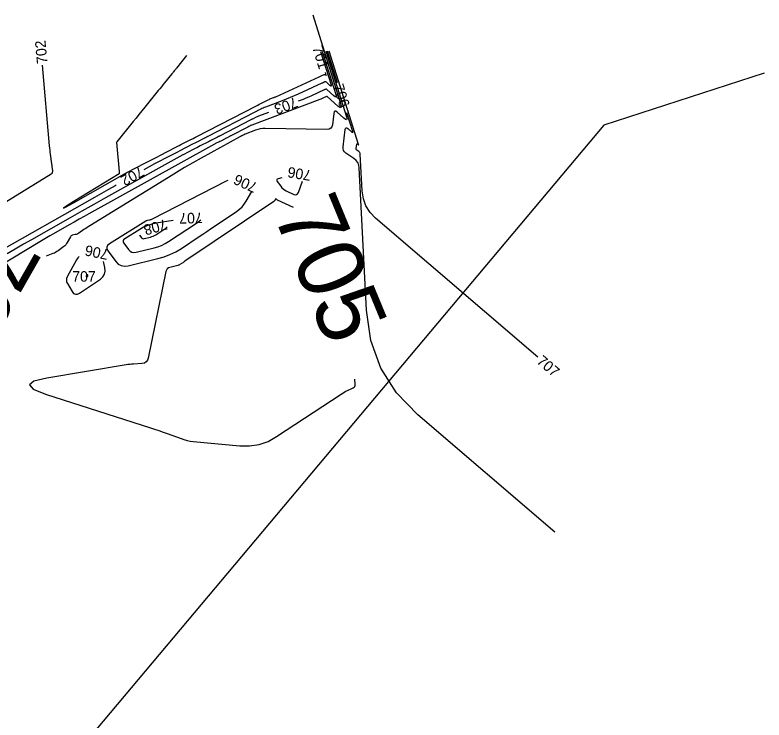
# Model space of a CAD drawing. Extents: x -468541894 to 3393103, y -306086142 to 1227927.
# Drawn here: x 1843241.8 to 1843525.9, y 539482.8 to 539750.1 of the extents above; entities that cross this region are included whole.
import ezdxf

# ---------------------------------------------------------------- set-up
doc = ezdxf.new("R2010")
doc.units = 0
for name, color, linetype in [('DT_X_Contour_Minor', 7, 'Continuous'), ('Level 19', 7, 'Continuous'), ('Level 40', 7, 'Continuous')]:
    doc.layers.add(name, color=color, linetype=linetype)

msp = doc.modelspace()

# ---------------------------------------------------------------- linework, layer by layer
at = {"layer": 'DT_X_Contour_Minor'}
for points in [[(1843354.69, 539750.11), (1843365.34, 539716.2), (1843365.54, 539715.31), (1843365.43, 539714.9), (1843365.01, 539714.97), (1843364.29, 539715.53), (1843360.23, 539719.22), (1843360.2, 539719.24), (1843360.18, 539719.25), (1843360.15, 539719.25), (1843360.12, 539719.24), (1843360.03, 539719.2), (1843360.01, 539719.19), (1843359.99, 539719.18), (1843359.97, 539719.17), (1843359.95, 539719.16), (1843358.6, 539718.54), (1843358.31, 539718.42), (1843358.02, 539718.29), (1843357.73, 539718.17), (1843357.43, 539718.06), (1843331.61, 539708.35), (1843331.45, 539708.29), (1843331.3, 539708.22), (1843331.14, 539708.15), (1843330.99, 539708.08), (1843330.49, 539707.82), (1843330.38, 539707.76), (1843330.27, 539707.71), (1843330.16, 539707.65), (1843330.06, 539707.6), (1843323.67, 539704.31), (1843323.62, 539704.28), (1843323.56, 539704.25), (1843323.51, 539704.22), (1843323.45, 539704.2), (1843323.28, 539704.1), (1843323.24, 539704.08), (1843323.2, 539704.07), (1843323.16, 539704.05), (1843323.12, 539704.03), (1843322.23, 539703.56), (1843322.03, 539703.46), (1843321.84, 539703.37), (1843321.65, 539703.27), (1843321.46, 539703.17), (1843319.8, 539702.31), (1843319.44, 539702.13), (1843319.08, 539701.94), (1843318.73, 539701.76), (1843318.37, 539701.58), (1843316.35, 539700.54), (1843316.34, 539700.53), (1843316.33, 539700.53), (1843316.33, 539700.52), (1843316.32, 539700.52), (1843316.29, 539700.51), (1843316.29, 539700.5), (1843316.28, 539700.5), (1843316.28, 539700.5), (1843316.27, 539700.49), (1843269.84, 539674.71), (1843267.97, 539673.67), (1843266.11, 539672.63), (1843264.25, 539671.59), (1843262.4, 539670.54), (1843256.34, 539667.1), (1843255.05, 539666.36), (1843253.76, 539665.61), (1843252.47, 539664.86), (1843251.19, 539664.09), (1843225.15, 539648.36)], [(1843359.68, 539736.36), (1843367.47, 539711.54), (1843367.65, 539710.75), (1843367.55, 539710.39), (1843367.18, 539710.45), (1843366.54, 539710.95), (1843364.01, 539713.25), (1843363.52, 539713.6), (1843363.14, 539713.63), (1843362.88, 539713.36), (1843362.73, 539712.78), (1843362.19, 539708.5), (1843361.97, 539707.7), (1843361.55, 539707.13), (1843360.93, 539706.8), (1843360.11, 539706.7), (1843336.66, 539707.08), (1843335.74, 539707.05), (1843334.83, 539706.94), (1843333.94, 539706.74), (1843333.07, 539706.46), (1843329.05, 539704.95), (1843329.03, 539704.94), (1843329.01, 539704.93), (1843328.99, 539704.92), (1843328.97, 539704.91), (1843328.9, 539704.88), (1843328.89, 539704.87), (1843328.88, 539704.86), (1843328.86, 539704.86), (1843328.85, 539704.85), (1843328.02, 539704.42), (1843328.01, 539704.42), (1843328.01, 539704.42), (1843328, 539704.41), (1843327.99, 539704.41), (1843327.97, 539704.4), (1843327.97, 539704.39), (1843327.96, 539704.39), (1843327.96, 539704.39), (1843327.95, 539704.39), (1843327.83, 539704.33), (1843327.81, 539704.31), (1843327.78, 539704.3), (1843327.76, 539704.29), (1843327.73, 539704.28), (1843327.52, 539704.17), (1843327.47, 539704.14), (1843327.43, 539704.12), (1843327.38, 539704.09), (1843327.34, 539704.07), (1843327.07, 539703.94), (1843327.07, 539703.93), (1843327.07, 539703.93), (1843327.07, 539703.93), (1843327.07, 539703.93), (1843327.07, 539703.93), (1843327.07, 539703.93), (1843327.06, 539703.93), (1843327.06, 539703.93), (1843327.06, 539703.93), (1843312.39, 539695.78), (1843309.26, 539694.02), (1843306.14, 539692.22), (1843303.05, 539690.39), (1843299.98, 539688.52), (1843270.14, 539670.15), (1843269.58, 539669.8), (1843269.02, 539669.45), (1843268.47, 539669.08), (1843267.92, 539668.71), (1843265.96, 539667.37), (1843265.66, 539667.18), (1843265.34, 539667.03), (1843265.01, 539666.9), (1843264.67, 539666.81), (1843263.52, 539666.57), (1843263.29, 539666.5), (1843263.09, 539666.38), (1843262.93, 539666.22), (1843262.79, 539666.02), (1843261.63, 539663.86), (1843261.36, 539663.41), (1843261.05, 539663), (1843260.69, 539662.63), (1843260.29, 539662.3), (1843258.17, 539660.7), (1843257.71, 539660.38), (1843257.22, 539660.09), (1843256.72, 539659.84), (1843256.2, 539659.63), (1843253.64, 539658.68)], [(1843357.69, 539736.29), (1843361.66, 539723.63), (1843361.74, 539723.28), (1843361.7, 539723.11), (1843361.53, 539723.14), (1843361.24, 539723.37), (1843359.89, 539724.6), (1843359.74, 539724.7), (1843359.58, 539724.75), (1843359.42, 539724.75), (1843359.24, 539724.7), (1843358.66, 539724.43), (1843358.53, 539724.37), (1843358.41, 539724.31), (1843358.28, 539724.26), (1843358.15, 539724.2), (1843349.19, 539720.09), (1843347.68, 539719.42), (1843346.16, 539718.77), (1843344.63, 539718.15), (1843343.09, 539717.55), (1843336.74, 539715.17), (1843336.3, 539715), (1843335.87, 539714.81), (1843335.44, 539714.61), (1843335.02, 539714.4), (1843333.65, 539713.7), (1843333.36, 539713.55), (1843333.06, 539713.4), (1843332.77, 539713.24), (1843332.47, 539713.09), (1843314.98, 539704.08), (1843314.83, 539704), (1843314.68, 539703.92), (1843314.53, 539703.85), (1843314.38, 539703.77), (1843313.89, 539703.52), (1843313.78, 539703.46), (1843313.68, 539703.41), (1843313.57, 539703.36), (1843313.47, 539703.3), (1843311.01, 539702.04), (1843310.49, 539701.77), (1843309.96, 539701.49), (1843309.43, 539701.22), (1843308.91, 539700.95), (1843304.35, 539698.6), (1843303.37, 539698.1), (1843302.4, 539697.6), (1843301.42, 539697.1), (1843300.45, 539696.59), (1843294.9, 539693.74), (1843294.88, 539693.73), (1843294.86, 539693.71), (1843294.84, 539693.7), (1843294.81, 539693.69), (1843294.74, 539693.66), (1843294.73, 539693.65), (1843294.71, 539693.64), (1843294.7, 539693.63), (1843294.68, 539693.62), (1843290.67, 539691.39)], [(1843358.35, 539736.32), (1843363.5, 539719.92), (1843363.64, 539719.29), (1843363.56, 539719.01), (1843363.27, 539719.06), (1843362.76, 539719.45), (1843360.06, 539721.91), (1843359.97, 539721.97), (1843359.88, 539722), (1843359.78, 539722), (1843359.68, 539721.97), (1843359.34, 539721.81), (1843359.27, 539721.78), (1843359.2, 539721.75), (1843359.12, 539721.71), (1843359.05, 539721.68), (1843354.19, 539719.45), (1843353.14, 539718.99), (1843352.09, 539718.54), (1843351.03, 539718.1), (1843349.96, 539717.69), (1843349.16, 539717.39)], [(1843364.09, 539724.42), (1843360.34, 539736.38)], [(1843440.11, 539620.34), (1843378.53, 539673.1), (1843376.44, 539675.27), (1843374.9, 539677.71), (1843373.91, 539680.42), (1843373.47, 539683.4), (1843372.76, 539697.37), (1843372.72, 539697.65), (1843372.62, 539697.89), (1843372.46, 539698.1), (1843372.25, 539698.28), (1843371.46, 539698.82), (1843371.32, 539698.94), (1843371.22, 539699.09), (1843371.18, 539699.26), (1843371.18, 539699.45), (1843371.39, 539701.13), (1843371.42, 539701.25), (1843371.48, 539701.31), (1843371.56, 539701.3), (1843371.66, 539701.23), (1843372.04, 539700.88), (1843372.1, 539700.83), (1843372.14, 539700.83), (1843372.15, 539700.86), (1843372.13, 539700.95), (1843361, 539736.4)], [(1843306.88, 539734.71), (1843302.99, 539729.89), (1843302.82, 539729.68), (1843302.65, 539729.47), (1843302.48, 539729.26), (1843302.31, 539729.05), (1843301.76, 539728.37), (1843301.64, 539728.22), (1843301.52, 539728.08), (1843301.4, 539727.93), (1843301.28, 539727.78), (1843298.5, 539724.35), (1843297.91, 539723.61), (1843297.31, 539722.88), (1843296.72, 539722.14), (1843296.12, 539721.41), (1843291.01, 539715.09), (1843289.92, 539713.74), (1843288.82, 539712.38), (1843287.72, 539711.03), (1843286.63, 539709.67), (1843280.46, 539702.05), (1843280.44, 539702.02), (1843280.41, 539701.99), (1843280.39, 539701.96), (1843280.37, 539701.93), (1843280.29, 539701.84), (1843280.27, 539701.81), (1843280.26, 539701.79), (1843280.26, 539701.77), (1843280.26, 539701.74), (1843281.25, 539690.74), (1843281.25, 539690.65), (1843281.26, 539690.56), (1843281.27, 539690.48), (1843281.29, 539690.39), (1843281.32, 539690.11), (1843281.32, 539690.05), (1843281.31, 539690), (1843281.28, 539689.96), (1843281.24, 539689.93), (1843263.86, 539679.22), (1843261.08, 539677.48), (1843260.18, 539676.85), (1843261.16, 539677.34), (1843264.02, 539678.94), (1843282.4, 539689.36), (1843282.58, 539689.46), (1843282.75, 539689.55), (1843282.93, 539689.65), (1843283.11, 539689.75), (1843283.88, 539690.18), (1843283.9, 539690.19), (1843283.93, 539690.21), (1843283.96, 539690.23), (1843283.99, 539690.24), (1843284.08, 539690.29), (1843284.1, 539690.3), (1843284.12, 539690.31), (1843284.14, 539690.32), (1843284.16, 539690.33), (1843291.09, 539693.9), (1843292.57, 539694.66), (1843294.06, 539695.43), (1843295.54, 539696.19), (1843297.02, 539696.96), (1843302.55, 539699.8), (1843303.28, 539700.18), (1843304.02, 539700.56), (1843304.75, 539700.94), (1843305.49, 539701.32), (1843308.53, 539702.88), (1843308.72, 539702.98), (1843308.92, 539703.08), (1843309.12, 539703.19), (1843309.31, 539703.29), (1843309.96, 539703.62), (1843310.09, 539703.69), (1843310.23, 539703.76), (1843310.37, 539703.83), (1843310.51, 539703.9), (1843333.35, 539715.67), (1843333.9, 539715.96), (1843334.46, 539716.24), (1843335.01, 539716.52), (1843335.56, 539716.81)], [(1843216.09, 539665.61), (1843255.53, 539689.92), (1843255.84, 539690.16), (1843256.04, 539690.45), (1843256.13, 539690.79), (1843256.13, 539691.18), (1843255.94, 539692.53), (1843255.9, 539692.82), (1843255.86, 539693.11), (1843255.82, 539693.4), (1843255.78, 539693.69), (1843255.28, 539697.31), (1843255.18, 539698.09), (1843255.09, 539698.87), (1843255, 539699.65), (1843254.93, 539700.43), (1843252.18, 539731.12)], [(1843335.56, 539716.81), (1843337.54, 539717.83), (1843337.84, 539717.98), (1843338.15, 539718.12), (1843338.46, 539718.25), (1843338.78, 539718.38), (1843339.82, 539718.77), (1843340.04, 539718.85), (1843340.26, 539718.94), (1843340.48, 539719.04), (1843340.69, 539719.13), (1843357.11, 539726.65), (1843357.36, 539726.77), (1843357.61, 539726.88), (1843357.87, 539727), (1843358.12, 539727.12), (1843359.09, 539727.56), (1843359.2, 539727.59), (1843359.3, 539727.59), (1843359.39, 539727.56), (1843359.49, 539727.5), (1843359.77, 539727.24), (1843359.82, 539727.2), (1843359.85, 539727.19), (1843359.86, 539727.22), (1843359.85, 539727.28), (1843359.54, 539728.26)], [(1843337.92, 539713.17), (1843334.18, 539711.76), (1843333.88, 539711.64), (1843333.58, 539711.52), (1843333.29, 539711.38), (1843333, 539711.24), (1843332.07, 539710.76), (1843331.87, 539710.66), (1843331.67, 539710.55), (1843331.47, 539710.45), (1843331.27, 539710.35), (1843319.32, 539704.19), (1843319.22, 539704.14), (1843319.12, 539704.09), (1843319.02, 539704.04), (1843318.92, 539703.98), (1843318.58, 539703.81), (1843318.51, 539703.77), (1843318.44, 539703.74), (1843318.37, 539703.7), (1843318.3, 539703.66), (1843316.62, 539702.8), (1843316.26, 539702.61), (1843315.9, 539702.43), (1843315.54, 539702.24), (1843315.18, 539702.06), (1843312.07, 539700.46), (1843311.41, 539700.12), (1843310.74, 539699.77), (1843310.08, 539699.43), (1843309.41, 539699.09), (1843305.62, 539697.14), (1843305.61, 539697.13), (1843305.6, 539697.12), (1843305.58, 539697.11), (1843305.57, 539697.11), (1843305.52, 539697.08), (1843305.51, 539697.08), (1843305.5, 539697.07), (1843305.49, 539697.07), (1843305.48, 539697.06), (1843280.63, 539683.26), (1843276.15, 539680.76), (1843271.67, 539678.26), (1843267.19, 539675.74), (1843262.73, 539673.22), (1843248.07, 539664.91), (1843244.99, 539663.15), (1843241.92, 539661.37), (1843238.86, 539659.56)], [(1843446.48, 539554), (1843394.59, 539598.45), (1843386.51, 539606.82), (1843380.56, 539616.23), (1843376.74, 539626.7), (1843375.06, 539638.21), (1843372.31, 539692.14), (1843372.14, 539693.2), (1843371.76, 539694.14), (1843371.16, 539694.96), (1843370.34, 539695.66), (1843367.3, 539697.73), (1843366.75, 539698.21), (1843366.38, 539698.78), (1843366.2, 539699.43), (1843366.2, 539700.17), (1843367.02, 539706.64), (1843367.14, 539707.12), (1843367.36, 539707.34), (1843367.67, 539707.31), (1843368.07, 539707.03), (1843369.52, 539705.7), (1843369.78, 539705.5), (1843369.93, 539705.48), (1843369.97, 539705.62), (1843369.9, 539705.94), (1843367.69, 539712.97)], [(1843322.56, 539687.33), (1843321.89, 539687.06), (1843293.79, 539672.63), (1843293.56, 539672.52), (1843293.33, 539672.44), (1843293.1, 539672.37), (1843292.86, 539672.32), (1843292.06, 539672.2), (1843291.89, 539672.16), (1843291.73, 539672.11), (1843291.58, 539672.05), (1843291.43, 539671.96), (1843277.62, 539663.31), (1843276.93, 539662.73), (1843276.62, 539662.07), (1843276.68, 539661.35), (1843277.11, 539660.55)], [(1843342.99, 539688.36), (1843341.61, 539687.97), (1843341.24, 539687.8), (1843341.06, 539687.58), (1843341.07, 539687.29), (1843341.26, 539686.93)], [(1843280.18, 539685.56), (1843279.83, 539685.37), (1843277.21, 539683.91), (1843274.6, 539682.44), (1843271.99, 539680.96), (1843232.97, 539658.85)], [(1843341.26, 539686.93), (1843342.58, 539685.14), (1843343.01, 539684.62), (1843343.5, 539684.17), (1843344.04, 539683.78), (1843344.63, 539683.46), (1843347.55, 539682.1), (1843348.13, 539681.93), (1843348.61, 539681.99), (1843348.99, 539682.29), (1843349.27, 539682.82), (1843350.8, 539687.07)], [(1843277.11, 539660.55), (1843280.02, 539656.67), (1843280.98, 539655.68), (1843282.08, 539655.07), (1843283.32, 539654.84), (1843284.69, 539655), (1843295.95, 539657.71), (1843298.31, 539658.39), (1843300.58, 539659.27), (1843302.77, 539660.34), (1843304.88, 539661.61), (1843311.61, 539666.08), (1843313.05, 539667.04), (1843314.49, 539668), (1843315.93, 539668.96), (1843317.37, 539669.93), (1843325.83, 539675.62), (1843326.92, 539676.44), (1843327.9, 539677.37), (1843328.77, 539678.39), (1843329.53, 539679.53), (1843331.68, 539683.15)], [(1843347.44, 539677.09), (1843341.35, 539679.92), (1843341.27, 539679.97), (1843341.19, 539680.02), (1843341.12, 539680.09), (1843341.06, 539680.16), (1843340.87, 539680.41), (1843340.83, 539680.45), (1843340.79, 539680.47), (1843340.76, 539680.45), (1843340.72, 539680.41), (1843340.38, 539679.83), (1843340.3, 539679.71), (1843340.21, 539679.6), (1843340.1, 539679.5), (1843339.99, 539679.42), (1843306.19, 539656.7), (1843305.94, 539656.53), (1843305.68, 539656.36), (1843305.43, 539656.19), (1843305.18, 539656.02), (1843304.34, 539655.47), (1843304.16, 539655.36), (1843303.97, 539655.27), (1843303.78, 539655.19), (1843303.57, 539655.13), (1843300.57, 539654.41), (1843299.99, 539654.19), (1843299.54, 539653.85), (1843299.21, 539653.39), (1843299.02, 539652.8), (1843292.34, 539620.02), (1843292.05, 539619.16), (1843291.55, 539618.53), (1843290.85, 539618.13), (1843289.96, 539617.95), (1843286.71, 539617.75), (1843286.02, 539617.7), (1843285.32, 539617.63), (1843284.63, 539617.54), (1843283.95, 539617.43), (1843253.83, 539612.43), (1843248.96, 539611.25), (1843247.26, 539609.83), (1843248.74, 539608.18), (1843253.38, 539606.31)], [(1843301.79, 539672.14), (1843295.39, 539671.13), (1843293.73, 539670.79), (1843292.13, 539670.28), (1843290.59, 539669.62), (1843289.11, 539668.79), (1843283.42, 539665.22), (1843283, 539664.86), (1843282.81, 539664.46), (1843282.84, 539664.02), (1843283.11, 539663.54)], [(1843283.11, 539663.54), (1843284.88, 539661.17), (1843285.47, 539660.57), (1843286.14, 539660.2), (1843286.89, 539660.06), (1843287.73, 539660.15), (1843294.58, 539661.81), (1843296.03, 539662.22), (1843297.42, 539662.76), (1843298.75, 539663.41), (1843300.04, 539664.19), (1843310.63, 539671.22), (1843312.23, 539672.45)], [(1843289.11, 539666.52), (1843289.75, 539665.67), (1843289.96, 539665.46), (1843290.2, 539665.32), (1843290.47, 539665.27), (1843290.77, 539665.31), (1843293.23, 539665.9), (1843293.75, 539666.05), (1843294.25, 539666.24), (1843294.73, 539666.48), (1843295.19, 539666.76), (1843299, 539669.28), (1843299.57, 539669.73)], [(1843289.01, 539666.69), (1843289.11, 539666.52)], [(1843266.17, 539658.57), (1843265.6, 539658.02), (1843265.07, 539657.23), (1843261.62, 539650.79), (1843261.36, 539650.14), (1843261.29, 539649.5), (1843261.39, 539648.86), (1843261.68, 539648.23)], [(1843261.68, 539648.23), (1843263.46, 539645.28), (1843264.04, 539644.56), (1843264.71, 539644.22), (1843265.46, 539644.25), (1843266.29, 539644.65), (1843274.18, 539649.97), (1843275.17, 539650.84), (1843275.79, 539651.85), (1843276.03, 539653.01), (1843275.9, 539654.32), (1843275.35, 539656.69)], [(1843268.77, 539650.98), (1843268.86, 539650.84), (1843268.89, 539650.8), (1843268.92, 539650.79), (1843268.95, 539650.79), (1843268.99, 539650.81), (1843269.37, 539651.06), (1843269.41, 539651.1), (1843269.44, 539651.15), (1843269.46, 539651.21), (1843269.45, 539651.27), (1843269.4, 539651.48), (1843269.38, 539651.52), (1843269.36, 539651.55), (1843269.33, 539651.56), (1843269.29, 539651.56), (1843269.07, 539651.51), (1843269.03, 539651.5), (1843268.99, 539651.47), (1843268.96, 539651.44), (1843268.93, 539651.41), (1843268.77, 539651.1), (1843268.76, 539651.07), (1843268.75, 539651.04), (1843268.76, 539651.01), (1843268.77, 539650.98)], [(1843253.38, 539606.31), (1843293.13, 539593.61), (1843294.74, 539593.08), (1843296.35, 539592.54), (1843297.96, 539591.97), (1843299.55, 539591.39), (1843304.76, 539589.47), (1843305.89, 539589.09), (1843307.03, 539588.79), (1843308.19, 539588.57), (1843309.36, 539588.42), (1843327.06, 539586.75), (1843330.78, 539586.7), (1843334.34, 539587.26), (1843337.75, 539588.44), (1843341.01, 539590.23), (1843365.48, 539606.37), (1843366.08, 539606.75), (1843366.69, 539607.11), (1843367.31, 539607.44), (1843367.94, 539607.75), (1843370.03, 539608.72), (1843370.42, 539608.96), (1843370.69, 539609.28), (1843370.83, 539609.66), (1843370.86, 539610.12), (1843370.72, 539612.02)]]:
    msp.add_lwpolyline(points, dxfattribs=at)
at = {"layer": 'Level 40'}
for p, q in [((1843525.86, 539728.01), (1843465.17, 539708.3)), ((1843465.17, 539708.3), (1843217.11, 539413.21))]:
    msp.add_line(p, q, dxfattribs=at)

# ---------------------------------------------------------------- texts
at = {"layer": 'Level 19'}
for s, height, rotation, p in [('702', 4, 95.1242, (1843254.13, 539731.75)), ('701', 4, 287.4329, (1843354.47, 539737.73)), ('706', 4, 287.4329, (1843362.38, 539723.22)), ('703', 4, 200.5977, (1843348.05, 539719.11)), ('702', 4, 209.0579, (1843289.3, 539692.92)), ('706', 4, 170.6101, (1843354.38, 539691.11)), ('706', 4, 155.4075, (1843334.07, 539686.16)), ('705', 25, 292.4239, (1843339.41, 539675.15)), ('707', 4, 181.7073, (1843312.93, 539675.22)), ('708', 4, 196.0134, (1843298.81, 539672.77)), ('705', 25, 240.3502, (1843230.64, 539672.04)), ('706', 4, 168.4448, (1843277.55, 539661.11)), ('707', 4, 319.4103, (1843439.36, 539618.35))]:
    msp.add_text(s, height=height, rotation=rotation, dxfattribs=at).set_placement(p)
msp.add_text('707', height=4, dxfattribs=at).set_placement((1843263.5, 539648.98))

doc.saveas('drawing.dxf')
